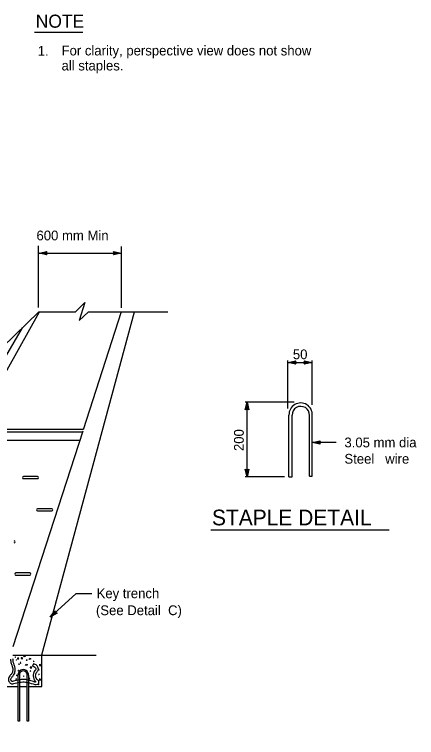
# Model space of a CAD drawing. Extents: x 6712486 to 6713732, y 1869200 to 1869925.
# Drawn here: x 6713475.8 to 6713732.1, y 1869308.8 to 1869770 of the extents above; entities that cross this region are included whole.
import ezdxf

# ---------------------------------------------------------------- set-up
doc = ezdxf.new("R2010")
doc.units = 0
for name, color, linetype in [('56 Stg 3 Anno', 7, 'Continuous'), ('57 Undefined', 7, 'Continuous'), ('60 Nongeo Data', 7, 'Continuous'), ('63 Undefined', 7, 'Continuous')]:
    doc.layers.add(name, color=color, linetype=linetype)

msp = doc.modelspace()

# ---------------------------------------------------------------- linework, layer by layer
at = {"layer": '56 Stg 3 Anno'}
for p, q in [((6713491.48, 1869617.7), (6713496.48, 1869618.81)), ((6713496.48, 1869616.59), (6713491.48, 1869617.7)), ((6713491.48, 1869617.7), (6713491.48, 1869617.7)), ((6713496.3, 1869616.88), (6713492.63, 1869617.7)), ((6713492.64, 1869617.7), (6713496.28, 1869618.51)), ((6713493.78, 1869617.7), (6713496.13, 1869618.22)), ((6713496.1, 1869617.18), (6713493.78, 1869617.7)), ((6713494.93, 1869617.7), (6713495.94, 1869617.92)), ((6713495.95, 1869617.47), (6713494.93, 1869617.7)), ((6713496.48, 1869618.81), (6713495.81, 1869617.7)), ((6713495.81, 1869617.7), (6713496.48, 1869616.59)), ((6713496.48, 1869618.81), (6713496.48, 1869618.81)), ((6713496.48, 1869616.59), (6713496.48, 1869616.59)), ((6713539.56, 1869617.7), (6713538.9, 1869618.82)), ((6713538.9, 1869618.82), (6713538.9, 1869618.82)), ((6713538.9, 1869618.82), (6713543.89, 1869617.7)), ((6713543.89, 1869617.7), (6713538.9, 1869616.59)), ((6713538.9, 1869616.59), (6713539.56, 1869617.7)), ((6713538.9, 1869616.59), (6713538.9, 1869616.59)), ((6713539.08, 1869618.52), (6713542.74, 1869617.7)), ((6713542.74, 1869617.7), (6713539.09, 1869616.89)), ((6713541.59, 1869617.7), (6713539.24, 1869617.18)), ((6713539.27, 1869618.22), (6713541.59, 1869617.7)), ((6713539.42, 1869617.93), (6713540.44, 1869617.7)), ((6713540.44, 1869617.7), (6713539.44, 1869617.48)), ((6713543.89, 1869617.7), (6713543.89, 1869617.7)), ((6713650.12, 1869518.73), (6713650.12, 1869549.27)), ((6713650.12, 1869548.02), (6713655.12, 1869549.13)), ((6713650.12, 1869548.02), (6713665.48, 1869548.02)), ((6713655.12, 1869546.91), (6713650.12, 1869548.02)), ((6713650.12, 1869548.02), (6713650.12, 1869548.02)), ((6713654.94, 1869547.21), (6713651.27, 1869548.02)), ((6713651.28, 1869548.03), (6713654.92, 1869548.83)), ((6713652.42, 1869548.02), (6713654.78, 1869548.54)), ((6713654.74, 1869547.51), (6713652.42, 1869548.02)), ((6713653.57, 1869548.02), (6713654.58, 1869548.25)), ((6713654.6, 1869547.79), (6713653.57, 1869548.02)), ((6713655.12, 1869549.13), (6713654.45, 1869548.02)), ((6713654.45, 1869548.02), (6713655.12, 1869546.91)), ((6713655.12, 1869549.13), (6713655.12, 1869549.13)), ((6713655.12, 1869546.91), (6713655.12, 1869546.91)), ((6713661.15, 1869548.02), (6713660.49, 1869549.14)), ((6713660.49, 1869549.14), (6713660.49, 1869549.14)), ((6713660.49, 1869549.14), (6713665.48, 1869548.02)), ((6713665.48, 1869548.02), (6713660.49, 1869546.92)), ((6713660.49, 1869546.92), (6713661.15, 1869548.02)), ((6713660.49, 1869546.92), (6713660.49, 1869546.92)), ((6713660.67, 1869548.84), (6713664.33, 1869548.03)), ((6713664.32, 1869548.02), (6713660.68, 1869547.22)), ((6713663.18, 1869548.03), (6713660.83, 1869547.51)), ((6713660.86, 1869548.54), (6713663.18, 1869548.03)), ((6713661.01, 1869548.26), (6713662.03, 1869548.03)), ((6713662.03, 1869548.03), (6713661.02, 1869547.8)), ((6713665.48, 1869521.01), (6713665.48, 1869549.27)), ((6713665.48, 1869548.02), (6713665.48, 1869548.02)), ((6713654.15, 1869522.79), (6713622.82, 1869522.79)), ((6713622.95, 1869517.79), (6713624.06, 1869522.79)), ((6713623.25, 1869517.97), (6713624.06, 1869521.64)), ((6713623.54, 1869518.17), (6713624.06, 1869520.49)), ((6713623.83, 1869518.32), (6713624.06, 1869519.34)), ((6713624.06, 1869475.03), (6713624.06, 1869522.79)), ((6713624.06, 1869522.79), (6713624.06, 1869522.79)), ((6713624.06, 1869522.79), (6713625.17, 1869517.79)), ((6713624.06, 1869520.49), (6713624.58, 1869518.14)), ((6713624.06, 1869519.34), (6713624.29, 1869518.33)), ((6713624.07, 1869521.63), (6713624.87, 1869517.99)), ((6713624.06, 1869518.46), (6713622.95, 1869517.79)), ((6713622.95, 1869517.79), (6713622.95, 1869517.79)), ((6713625.17, 1869517.79), (6713624.06, 1869518.46)), ((6713625.17, 1869517.79), (6713625.17, 1869517.79)), ((6713665.66, 1869497), (6713670.66, 1869498.11)), ((6713680.89, 1869497), (6713665.66, 1869497)), ((6713670.66, 1869495.89), (6713665.66, 1869497)), ((6713665.66, 1869497), (6713665.66, 1869497)), ((6713670.47, 1869496.18), (6713666.81, 1869497)), ((6713666.82, 1869497), (6713670.46, 1869497.81)), ((6713667.96, 1869497), (6713670.31, 1869497.52)), ((6713670.28, 1869496.48), (6713667.96, 1869497)), ((6713669.11, 1869497), (6713670.12, 1869497.22)), ((6713670.13, 1869496.77), (6713669.11, 1869497)), ((6713670.66, 1869498.11), (6713669.99, 1869497)), ((6713669.99, 1869497), (6713670.66, 1869495.89)), ((6713670.66, 1869498.11), (6713670.66, 1869498.11)), ((6713670.66, 1869495.89), (6713670.66, 1869495.89)), ((6713624.06, 1869475.03), (6713622.96, 1869480.03)), ((6713622.96, 1869480.03), (6713622.96, 1869480.03)), ((6713622.96, 1869480.03), (6713624.06, 1869479.36)), ((6713624.06, 1869476.19), (6713623.26, 1869479.83)), ((6713624.07, 1869477.33), (6713623.55, 1869479.69)), ((6713624.07, 1869478.48), (6713623.84, 1869479.49)), ((6713624.06, 1869479.36), (6713625.18, 1869480.03)), ((6713625.18, 1869480.03), (6713624.06, 1869475.03)), ((6713624.88, 1869479.85), (6713624.07, 1869476.18)), ((6713624.58, 1869479.65), (6713624.07, 1869477.33)), ((6713624.3, 1869479.51), (6713624.07, 1869478.48)), ((6713625.18, 1869480.03), (6713625.18, 1869480.03)), ((6713647.92, 1869475.03), (6713622.82, 1869475.03)), ((6713624.06, 1869475.03), (6713624.06, 1869475.03))]:
    msp.add_line(p, q, dxfattribs=at)
at = {"layer": '57 Undefined'}
for p, q in [((6713488.54, 1869758.78), (6713519.46, 1869758.78)), ((6713600.97, 1869441.34), (6713714.7, 1869441.34))]:
    msp.add_line(p, q, dxfattribs=at)
at = {"layer": '60 Nongeo Data'}
for p, q in [((6713491.2, 1869583.05), (6713491.2, 1869622.52)), ((6713543.99, 1869582.82), (6713543.99, 1869622.07)), ((6713491.48, 1869617.7), (6713543.89, 1869617.7)), ((6713340.25, 1869308.78), (6713491.7, 1869580.33)), ((6713493.18, 1869361.64), (6713552.28, 1869580.34)), ((6713543.88, 1869580.29), (6713519.56, 1869505.04)), ((6713349.33, 1869345.55), (6713480.96, 1869570.1)), ((6713650.8, 1869475.16), (6713650.8, 1869514.48)), ((6713652.85, 1869475.16), (6713652.85, 1869514.36)), ((6713663.85, 1869475.54), (6713663.85, 1869514.22)), ((6713665.66, 1869475.54), (6713665.66, 1869514.3)), ((6713519.29, 1869504.18), (6713474.82, 1869366.61)), ((6713481.45, 1869473.92), (6713490.46, 1869473.92)), ((6713490.46, 1869475.29), (6713481.51, 1869475.29)), ((6713650.8, 1869475.16), (6713652.85, 1869475.16)), ((6713663.85, 1869475.54), (6713665.66, 1869475.54)), ((6713499.54, 1869454.75), (6713490.59, 1869454.74)), ((6713490.53, 1869453.37), (6713499.54, 1869453.37)), ((6713485.58, 1869413.75), (6713476.63, 1869413.75)), ((6713476.56, 1869412.38), (6713485.58, 1869412.38)), ((6713498.66, 1869385.48), (6713515.11, 1869400.62)), ((6713515.11, 1869400.62), (6713525.09, 1869400.62)), ((6713474.73, 1869361.31), (6713493.24, 1869361.31)), ((6713476.5, 1869360.15), (6713476.19, 1869360.01)), ((6713476.19, 1869360.01), (6713476.25, 1869360.07)), ((6713476.25, 1869360.07), (6713476.48, 1869359.73)), ((6713476.48, 1869359.73), (6713476.53, 1869360.18)), ((6713477.21, 1869358.48), (6713476.9, 1869358.34)), ((6713476.9, 1869358.34), (6713476.96, 1869358.39)), ((6713476.96, 1869358.39), (6713477.19, 1869358.05)), ((6713477.19, 1869358.05), (6713477.24, 1869358.5)), ((6713478.24, 1869359.55), (6713477.67, 1869359.38)), ((6713477.78, 1869359.49), (6713477.78, 1869358.93)), ((6713477.78, 1869358.93), (6713478.69, 1869359.04)), ((6713478.69, 1869359.04), (6713478.24, 1869359.55)), ((6713480.61, 1869359.72), (6713480.04, 1869359.55)), ((6713480.16, 1869359.66), (6713480.16, 1869359.1)), ((6713480.16, 1869359.1), (6713481.06, 1869359.21)), ((6713481.06, 1869359.21), (6713480.61, 1869359.72)), ((6713481.74, 1869360.34), (6713482.19, 1869361.07)), ((6713482.92, 1869360.73), (6713481.74, 1869360.34)), ((6713482.08, 1869361.18), (6713482.92, 1869360.73)), ((6713483.2, 1869358.42), (6713483.49, 1869358.03)), ((6713483.2, 1869358.42), (6713483.83, 1869358.25)), ((6713483.49, 1869358.03), (6713483.88, 1869358.08)), ((6713483.88, 1869358.08), (6713483.83, 1869358.25)), ((6713485.12, 1869358.59), (6713485.58, 1869359.32)), ((6713486.31, 1869358.98), (6713485.12, 1869358.59)), ((6713485.46, 1869359.44), (6713486.31, 1869358.98)), ((6713488.17, 1869357.12), (6713488.23, 1869357.58)), ((6713488.23, 1869357.58), (6713488.17, 1869357.52)), ((6713478.89, 1869355.78), (6713478.58, 1869355.64)), ((6713478.58, 1869355.64), (6713478.64, 1869355.7)), ((6713478.64, 1869355.7), (6713478.86, 1869355.36)), ((6713478.86, 1869355.36), (6713478.92, 1869355.81)), ((6713479.93, 1869356.56), (6713479.42, 1869356.56)), ((6713479.48, 1869356.62), (6713479.65, 1869356.11)), ((6713479.65, 1869356.11), (6713479.93, 1869356.56)), ((6713482.89, 1869354.68), (6713483.34, 1869355.41)), ((6713484.08, 1869355.07), (6713482.89, 1869354.68)), ((6713483.23, 1869355.53), (6713484.08, 1869355.07)), ((6713486.37, 1869353.8), (6713485.8, 1869353.63)), ((6713485.91, 1869353.74), (6713485.91, 1869353.18)), ((6713485.91, 1869353.18), (6713486.82, 1869353.29)), ((6713486.82, 1869353.29), (6713486.37, 1869353.8)), ((6713488.2, 1869357.55), (6713487.89, 1869357.41)), ((6713487.95, 1869357.46), (6713488.17, 1869357.12)), ((6713492.21, 1869355.3), (6713491.64, 1869355.13)), ((6713491.75, 1869355.24), (6713491.75, 1869354.68)), ((6713491.75, 1869354.68), (6713492.66, 1869354.79)), ((6713492.66, 1869354.79), (6713492.21, 1869355.3)), ((6713477.42, 1869348.59), (6713477.11, 1869348.45)), ((6713477.16, 1869348.5), (6713477.39, 1869348.17)), ((6713477.39, 1869348.17), (6713477.45, 1869348.62)), ((6713477.45, 1869348.62), (6713477.39, 1869348.56)), ((6713478.43, 1869351.62), (6713478.12, 1869351.48)), ((6713478.12, 1869351.48), (6713478.18, 1869351.54)), ((6713478.14, 1869319.31), (6713478.13, 1869348.7)), ((6713478.18, 1869351.54), (6713478.4, 1869351.2)), ((6713478.4, 1869351.2), (6713478.46, 1869351.65)), ((6713478.98, 1869348.69), (6713479, 1869319.31)), ((6713483.9, 1869319.27), (6713483.88, 1869348.62)), ((6713484.75, 1869348.58), (6713484.73, 1869319.27)), ((6713486.05, 1869351.37), (6713485.74, 1869351.23)), ((6713485.74, 1869351.23), (6713485.8, 1869351.29)), ((6713485.8, 1869351.29), (6713486.02, 1869350.95)), ((6713486.02, 1869350.95), (6713486.08, 1869351.4)), ((6713491.53, 1869352.14), (6713491.02, 1869352.14)), ((6713491.08, 1869352.2), (6713491.25, 1869351.69)), ((6713491.54, 1869349.16), (6713491.23, 1869349.02)), ((6713491.23, 1869349.02), (6713491.29, 1869349.08)), ((6713491.25, 1869351.69), (6713491.53, 1869352.14)), ((6713491.29, 1869349.08), (6713491.52, 1869348.74)), ((6713491.52, 1869348.74), (6713491.57, 1869349.19)), ((6713477.01, 1869346.29), (6713476.7, 1869346.15)), ((6713476.7, 1869346.15), (6713476.76, 1869346.2)), ((6713476.76, 1869346.2), (6713476.98, 1869345.87)), ((6713476.98, 1869345.87), (6713477.04, 1869346.32)), ((6713481.78, 1869348.11), (6713481.47, 1869347.97)), ((6713481.47, 1869347.97), (6713481.53, 1869348.02)), ((6713481.53, 1869348.02), (6713481.75, 1869347.68)), ((6713481.75, 1869347.68), (6713481.81, 1869348.14)), ((6713485.49, 1869346.5), (6713485.18, 1869346.36)), ((6713485.24, 1869346.42), (6713485.46, 1869346.08)), ((6713485.46, 1869346.08), (6713485.52, 1869346.53)), ((6713485.52, 1869346.53), (6713485.46, 1869346.48)), ((6713492.13, 1869346.09), (6713491.57, 1869345.92)), ((6713491.68, 1869346.03), (6713491.68, 1869345.47)), ((6713491.68, 1869345.47), (6713492.58, 1869345.58)), ((6713492.58, 1869345.58), (6713492.13, 1869346.09)), ((6713491.45, 1869342.94), (6713490.95, 1869342.94)), ((6713491, 1869342.99), (6713491.17, 1869342.48)), ((6713491.17, 1869342.48), (6713491.45, 1869342.94)), ((6713479, 1869319.31), (6713478.14, 1869319.31)), ((6713484.73, 1869319.27), (6713483.9, 1869319.27))]:
    msp.add_line(p, q, dxfattribs=at)
for points in [[(6713468, 1869557.59), (6713491.27, 1869580.29), (6713514.73, 1869580.29)], [(6713522.94, 1869580.29), (6713573.58, 1869580.29)], [(6713419.12, 1869476.98), (6713449.8, 1869505.57), (6713519.48, 1869505.57)], [(6713418.21, 1869475.13), (6713449.22, 1869503.89), (6713519.04, 1869503.89)], [(6713414.91, 1869469.9), (6713446.18, 1869498.38), (6713517.29, 1869498.38)], [(6713327.88, 1869320.88), (6713369.52, 1869361.31), (6713468.82, 1869361.33), (6713468.83, 1869341.38), (6713478.14, 1869341.38)], [(6713484.72, 1869341.39), (6713493.15, 1869341.39), (6713493.15, 1869361.38), (6713527.97, 1869361.37)], [(6713478.98, 1869341.38), (6713483.9, 1869341.39)]]:
    msp.add_lwpolyline(points, dxfattribs=at)
for centre, radius, start, end in [((6713481.54, 1869474.6), 0.685, 92.5576, 270), ((6713490.46, 1869474.6), 0.686, 270, 90), ((6713490.62, 1869454.06), 0.685, 92.5576, 270), ((6713499.54, 1869454.06), 0.686, 270, 90), ((6713475.66, 1869433.6), 0.686, 270, 90), ((6713476.66, 1869413.07), 0.685, 92.5576, 270), ((6713485.58, 1869413.07), 0.686, 270, 90)]:
    msp.add_arc(centre, radius, start, end, dxfattribs=at)
for centre, major_axis in [((6713658.23, 1869514.75), (0, -7.44)), ((6713658.35, 1869514.55), (0, -5.5)), ((6713481.44, 1869348.82), (0, -3.31)), ((6713481.44, 1869348.78), (0, -2.45))]:
    msp.add_ellipse(centre, major_axis=major_axis, ratio=0.999991, start_param=1.510257, end_param=4.748244, dxfattribs=at)
at = {"layer": '63 Undefined'}
for p, q in [((6713514.73, 1869580.29), (6713520.65, 1869586.26)), ((6713520.65, 1869586.26), (6713517.01, 1869574.9)), ((6713517.01, 1869574.9), (6713522.94, 1869580.29)), ((6713498.66, 1869385.48), (6713498.66, 1869385.48)), ((6713501.58, 1869389.68), (6713501.58, 1869389.68)), ((6713503.09, 1869388.04), (6713503.09, 1869388.04)), ((6713488.04, 1869355.75), (6713487.35, 1869354.39))]:
    msp.add_line(p, q, dxfattribs=at)
msp.add_lwpolyline([(6713503.09, 1869388.04), (6713498.66, 1869385.48), (6713501.58, 1869389.68), (6713501.65, 1869389.34), (6713499.51, 1869386.27), (6713502.76, 1869388.14), (6713502.43, 1869388.24), (6713500.35, 1869387.04), (6713501.72, 1869389), (6713501.79, 1869388.66), (6713501.2, 1869387.81), (6713502.1, 1869388.34), (6713501.84, 1869388.41), (6713501.58, 1869389.68), (6713501.84, 1869388.41)], close=True, dxfattribs=at)
for points in [[(6713473.33, 1869358.84), (6713473.42, 1869357.59), (6713473.85, 1869355.53), (6713474.72, 1869352.83), (6713474.72, 1869351.63), (6713473.96, 1869349.36), (6713472.77, 1869348.06), (6713472.23, 1869346.98), (6713472.23, 1869344.59), (6713472.55, 1869344), (6713473.02, 1869343.42), (6713473.96, 1869343.08), (6713475.37, 1869343.18), (6713479.16, 1869344.05), (6713481.21, 1869344.27), (6713484.38, 1869343.87), (6713488.77, 1869342.69), (6713490.6, 1869342.73), (6713491.15, 1869343.14), (6713491.27, 1869343.4), (6713491.36, 1869343.79), (6713491.29, 1869344.7), (6713489.99, 1869346.11), (6713489.34, 1869348.71), (6713490.2, 1869350.77), (6713490.85, 1869351.53), (6713490.96, 1869353.13), (6713489.99, 1869354.78), (6713488.04, 1869355.75)], [(6713487.35, 1869354.39), (6713488.9, 1869353.61), (6713489.41, 1869352.76), (6713489.36, 1869352.13), (6713488.89, 1869351.58), (6713487.73, 1869348.83), (6713488.6, 1869345.36), (6713489.13, 1869344.77), (6713489.3, 1869344.63), (6713489.26, 1869344.22), (6713489.1, 1869344.16), (6713488.79, 1869344.2), (6713487.92, 1869344.44), (6713484.67, 1869345.38), (6713481.23, 1869345.8), (6713478.91, 1869345.56), (6713475.14, 1869344.7), (6713474.18, 1869344.62), (6713473.94, 1869344.71), (6713473.82, 1869344.85), (6713473.75, 1869344.98), (6713473.75, 1869346.62), (6713474.04, 1869347.18), (6713475.3, 1869348.57), (6713476.24, 1869351.39), (6713476.24, 1869353.06), (6713475.33, 1869355.92), (6713474.93, 1869357.8), (6713474.86, 1869358.94)]]:
    msp.add_spline(points, degree=3, dxfattribs=at)

# ---------------------------------------------------------------- texts
at = {"layer": '57 Undefined'}
for s, height, p in [('NOTE', 8.327, (6713489.35, 1869761.58)), ('1.', 6.245, (6713490.64, 1869743.68)), ('For clarity, perspective view does not show ', 6.2451, (6713505.83, 1869743.89)), ('all staples.', 6.2451, (6713505.83, 1869734.31)), ('50', 6.245, (6713653.28, 1869550.11)), ('3.05 mm dia', 6.2451, (6713686.14, 1869493.88)), ('Steel   wire', 6.2451, (6713686.14, 1869483.47)), ('STAPLE DETAIL', 9.9921, (6713601.7, 1869444.14))]:
    msp.add_text(s, height=height, dxfattribs=at).set_placement(p)
msp.add_text('200', height=6.245, rotation=90, dxfattribs=at).set_placement((6713621.98, 1869491.55))
at = {"layer": '60 Nongeo Data'}
for s, height, p in [('600 mm Min', 6.245, (6713489.85, 1869625.91)), ('Key trench', 6.245, (6713528.17, 1869397.66)), ('(See Detail  C)', 6.2451, (6713527.76, 1869386.84))]:
    msp.add_text(s, height=height, dxfattribs=at).set_placement(p)

doc.saveas('drawing.dxf')
